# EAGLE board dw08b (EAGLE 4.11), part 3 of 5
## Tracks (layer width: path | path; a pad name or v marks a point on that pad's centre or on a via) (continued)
N_DATA07  (via drill 0.61) (continued)
  Bottom 0.305: v63.5,33.27 64.52,33.27 B20.M1 | v63.25,40.89 60.45,40.89 59.18,42.16 v58.17,42.16 | v26.42,85.85 30.48,85.85 30.73,86.11 32.26,86.11 38.61,92.46 42.16,92.46 42.42,92.2 43.18,92.2 43.43,92.46 43.69,92.46 44.45,93.22 44.45,95 44.2,95.25 44.2,98.04 44.7,98.55 v50.8,98.55 | v48.77,123.7 47.24,125.22 47.24,126.75 47.5,126.75 47.75,127 v48.77,127 | v48.77,130.05 49.02,129.79 50.55,129.79 51.05,130.3 53.34,130.3 53.85,129.79 56.9,129.79 57.4,130.3 v58.93,130.3 | v117.35,85.34 120.4,85.34 120.9,85.85 123.19,85.85 123.7,85.34 126.75,85.34 127.25,85.85 v130.3,85.85 | v130.3,82.55 133.1,82.55 133.35,82.3 136.4,82.3 136.65,82.55 139.45,82.55 139.7,82.3 142.75,82.3 143,82.55 145.8,82.55 146.05,82.3 149.1,82.3 149.35,82.55 152.15,82.55 152.4,82.3 155.45,82.3 155.7,82.55 158.5,82.55 158.75,82.3 161.8,82.3 162.05,82.55 164.85,82.55 165.35,82.04 v166.12,82.04 | v183.64,66.55 185.17,66.55 187.45,68.83 188.72,68.83 188.98,68.58 194.82,68.58 v195.07,68.83
N_DATA08  (via drill 0.61)
  Top 0.305: 193.8,61.72 193.8,16 195.33,14.48 195.33,11.68 B09.V2 | 193.8,61.72 193.8,79.76 194.56,80.52 A09.V2 | v13.97,85.85 14.22,86.11 v14.22,88.9 | v2.79,128.02 2.54,128.27 2.54,137.41 v2.79,137.67 | v26.42,139.7 v26.42,136.91 | v144.27,95.25 v144.27,98.04 | v193.55,61.72 193.8,61.72
  2 0.305: v14.22,88.9 13.97,88.65 4.32,98.3 4.32,98.55 1.02,101.85 1.02,127.25 1.78,128.02 v2.79,128.02 | v156.97,95.25 158.5,95.25 173.74,80.01 175.26,80.01 184.91,70.36 184.91,69.34 188.72,65.53 189.74,65.53 v193.55,61.72
  15 0.305: v59.18,30.99 53.34,36.83 53.34,37.08 52.58,37.85 50.8,37.85 41.66,46.99 41.66,48.51 41.15,49.02 40.64,49.02 31.5,58.17 31.5,58.67 13.72,76.45 13.72,77.22 v11.68,79.25 | v40.39,139.7 40.89,139.7 43.43,142.24 47.5,142.24 48.77,143.51 84.84,143.51 106.68,121.67 107.19,121.67 126.24,102.62 127.25,102.62 128.52,101.35 128.52,100.84 v131.57,97.79
  Bottom 0.305: v59.18,30.99 59.94,30.23 61.21,30.23 B20.N1 | v11.68,79.25 12.7,80.26 12.7,82.3 12.45,82.55 12.45,85.34 12.95,85.85 v13.97,85.85 | v2.79,137.67 3.3,138.18 20.57,138.18 21.84,136.91 v26.42,136.91 | v26.42,139.7 26.67,139.95 40.13,139.95 v40.39,139.7 | v131.57,97.79 131.83,98.04 133.1,98.04 133.6,98.55 142.49,98.55 143,98.04 v144.27,98.04 | v144.27,95.25 145.8,95.25 146.05,95 149.1,95 149.35,95.25 152.15,95.25 152.4,95 155.45,95 155.7,95.25 v156.97,95.25
N_DATA09  (via drill 0.61)
  Top 0.305: A10.D2 182.63,124.71 182.63,121.41 181.1,119.89 181.1,80.52 182.63,78.99 182.63,64.01 181.1,62.48 181.1,61.47 182.63,59.94 182.63,56.13 B10.D2 182.63,54.86 182.63,54.36 182.88,54.1 182.88,52.32 v183.13,52.07 | v66.8,12.7 66.8,21.84 66.29,22.35 66.29,26.16 65.79,26.67 B20.P1 | v71.12,9.14 v71.12,12.45 | v125.73,2.79 125.98,2.54 125.98,2.29 126.49,1.78 128.02,1.78 128.02,3.3 127.76,3.56 127.76,10.41 130.3,12.95 v130.3,13.72 | v144.02,12.7 144.53,13.21 v144.53,15.49 | v172.47,11.43 174.75,13.72 174.75,15.24 174.24,15.75 174.24,18.8 174.75,19.3 v174.75,20.57 | v175.77,32.77 175.77,35.05 174.75,36.07 174.75,43.18 175.01,43.43 v175.01,45.47
  2 0.305: v176.53,20.83 181.36,25.65 181.1,25.91 181.1,27.43 v175.77,32.77
  15 0.305: v106.68,9.14 107.19,9.14 107.44,9.4 109.22,9.4 112.52,6.1 115.82,6.1 119.13,2.79 120.14,2.79 120.4,2.54 121.92,2.54 v122.17,2.79 | v144.53,15.49 144.78,15.49 145.29,14.99 146.3,14.99 147.32,16 149.1,16 152.65,12.45 155.45,12.45 155.96,12.95 156.21,12.7 158.5,12.7 158.75,12.45 161.8,12.45 162.31,12.95 162.56,12.7 164.85,12.7 165.1,12.45 168.15,12.45 168.66,12.95 168.91,12.7 171.2,12.7 v172.47,11.43 | v175.01,45.47 175.77,45.47 182.37,52.07 v183.13,52.07
  Bottom 0.305: v66.8,12.7 69.6,12.7 69.85,12.45 v71.12,12.45 | v71.12,9.14 71.37,8.89 90.93,8.89 91.19,9.14 v106.68,9.14 | v125.73,2.79 v122.17,2.79 | v130.3,13.72 133.6,13.72 134.37,12.95 139.19,12.95 139.7,12.45 142.75,12.45 143,12.7 v144.02,12.7 | v174.75,20.57 175.01,20.83 v176.53,20.83
N_DATA10  (via drill 0.61)
  Top 0.305: v63.5,7.37 63.5,12.45 63.25,12.7 63.25,15.49 63.5,15.75 63.5,18.8 61.98,20.32 61.98,23.11 B20.R1 | v142.49,4.06 142.49,12.45 143,12.95 v143,27.43 | v184.15,28.7 184.15,31.5 183.9,31.75 183.9,34.8 184.15,35.05 184.15,37.85 183.9,38.1 183.9,41.15 v184.15,41.4 | v186.94,41.4 186.94,44.2 187.45,44.7 187.45,47.24 186.94,47.75 v186.94,49.28 | v184.15,105.66 184.15,107.7 183.9,107.95 183.9,110.74 184.15,111 184.15,114.05 183.9,114.3 183.9,117.09 184.15,117.35 184.15,117.86 185.67,119.38 185.67,121.67 A10.E2 | v165.1,104.9 164.85,104.65 164.85,101.6 165.1,101.35 165.1,98.55 163.83,97.28 v163.83,95.25 | v174.24,81.03 173.74,81.03 173.74,68.83 v174.24,68.33 | v185.67,56.9 185.67,53.09 B10.E2
  2 0.305: v186.94,49.28 186.94,51.05 186.18,51.82 B10.E2 | v174.24,68.33 180.09,62.48 180.59,62.48 181.1,61.98 181.1,61.47 v185.67,56.9
  15 0.305: v115.82,7.11 119.38,3.56 v120.9,3.56 | v160.27,95 160.27,94.49 173.74,81.03 v174.24,81.03
  Bottom 0.305: v63.5,7.37 89.41,7.37 89.92,6.86 115.57,6.86 v115.82,7.11 | v120.9,3.56 121.16,3.81 122.94,3.81 123.44,4.32 142.24,4.32 v142.49,4.06 | v143,27.43 143.76,28.19 145.8,28.19 146.3,28.7 v184.15,28.7 | v186.94,41.4 v184.15,41.4 | v184.15,105.66 183.64,105.16 183.13,105.16 182.88,104.9 v165.1,104.9 | v163.83,95.25 161.8,95.25 161.54,95 v160.27,95
N_DATA11  (via drill 0.61)
  Top 0.305: A10.H2 185.67,115.32 185.67,112.01 187.2,110.49 187.2,51.05 185.67,49.53 185.67,46.74 B10.H2 | v123.7,11.43 125.22,12.95 126.75,12.95 126.75,15.75 127,16 v127,17.02 | v135.64,11.68 136.65,12.7 v136.65,13.97 | v139.45,13.97 139.45,15.75 139.7,16 v139.7,17.78 | v177.55,13.97 177.55,14.48 178.56,15.49 178.56,17.53 v178.82,17.78 | v176.02,40.89 v176.02,39.12
  2 0.305: v110.24,16 111,16 114.55,12.45 117.35,12.45 117.86,12.95 118.11,12.7 119.38,12.7 v120.65,11.43 | v130.05,17.02 133.35,13.72 133.6,13.72 v135.64,11.68 | v178.82,17.78 177.55,19.05 177.55,20.83 182.12,25.4 182.12,25.91 181.86,26.16 181.86,27.69 177.55,32 177.55,34.8 178.05,35.31 177.8,35.56 177.8,37.34 v176.02,39.12
  15 0.305: v77.72,12.45 v69.85,20.32 | v141.99,17.78 143.26,19.05 145.8,19.05 148.08,16.76 149.35,16.76 150.62,15.49 152.15,15.49 152.91,16.26 153.16,16 155.45,16 155.96,15.49 158.5,15.49 162.05,19.05 164.85,19.05 170.43,13.46 171.45,13.46 172.47,12.45 174.5,12.45 176.28,14.22 176.53,13.97 v177.55,13.97 | v179.07,41.4 183.13,45.47 185.17,45.47 B10.H2
  Bottom 0.305: v69.85,20.32 69.6,20.57 65.79,20.57 B20.S1 | v77.72,12.45 79.25,12.45 79.5,12.7 82.3,12.7 82.55,12.45 85.6,12.45 85.85,12.7 88.65,12.7 88.9,12.45 91.95,12.45 92.2,12.7 95,12.7 95.25,12.45 98.3,12.45 98.55,12.7 101.35,12.7 101.6,12.45 104.39,12.45 106.43,14.48 107.7,14.48 109.22,16 v110.24,16 | v123.7,11.43 v120.65,11.43 | v130.05,17.02 v127,17.02 | v139.45,13.97 v136.65,13.97 | v141.99,17.78 v139.7,17.78 | v176.02,40.89 177.55,40.89 178.05,41.4 v179.07,41.4
N_DATAIN  (via drill 0.61)
  Top 0.305: v103.38,35.05 103.38,36.58 103.12,36.83 103.12,39.12 B17.K1 | v111.25,27.18 111.25,12.7 110.74,12.19 v110.74,9.4 | v212.34,7.62 212.34,12.45 212.85,12.95 212.85,28.19 211.84,29.21 211.84,33.02 B08.M2 211.07,34.04 211.07,36.32 212.85,38.1 v212.85,40.89 | v190.5,101.35 190.5,98.3 190.25,98.04 190.25,95.25 190.5,95 190.5,91.95 190.25,91.69 190.25,88.9 190.5,88.65 190.5,85.6 190.25,85.34 190.25,82.55 190.5,82.3 190.5,68.58 189.23,67.31 v189.23,64.52
  2 0.305: v111.25,27.18 v103.38,35.05 | v189.23,64.52 v212.85,40.89
  Bottom 0.305: v110.74,9.4 111,9.14 117.86,9.14 118.11,8.89 161.29,8.89 161.8,8.38 166.37,8.38 166.62,8.64 169.16,8.64 170.69,7.11 202.18,7.11 202.69,7.62 v212.34,7.62 | v190.5,101.35 193.29,101.35 193.55,101.6 196.6,101.6 196.85,101.35 199.64,101.35 199.9,101.6 202.95,101.6 203.2,101.35 205.99,101.35 207.77,103.12 210.57,103.12 A08.M2
N_EXTA0  (via drill 0.61)
  Top 0.305: A11.H2 172.97,115.32 172.97,111.51 174.5,109.98 174.5,82.8 172.97,81.28 172.97,67.06 174.5,65.53 174.5,51.05 172.97,49.53 172.97,46.74 B11.H2 172.97,45.47 v172.97,41.4 | v129.79,22.86 129.79,25.15 130.3,25.65 v130.3,26.92 | v133.1,27.18 133.1,28.45 133.6,28.96 v133.6,29.72 | v146.05,22.35 146.05,25.15 145.8,25.4 145.8,28.45 146.05,28.7 v146.05,29.72 | v148.84,29.72 148.84,31.5 149.35,32 v149.35,32.77 | v161.04,30.48 161.54,30.99 161.54,31.5 162.05,32 v162.05,40.89
  2 0.305: v133.6,29.72 134.62,28.7 135.13,28.7 140.97,22.86 v140.97,22.35 | v156.21,32 157.48,32 157.99,32.51 159,32.51 v161.04,30.48
  Bottom 0.305: v129.79,22.86 129.54,22.61 125.98,22.61 125.73,22.35 124.97,22.35 124.71,22.61 119.63,22.61 119.38,22.35 108.2,22.35 107.7,21.84 104.14,21.84 103.63,21.34 B17.S1 | v130.3,26.92 130.56,27.18 v133.1,27.18 | v146.05,22.35 v140.97,22.35 | v148.84,29.72 v146.05,29.72 | v149.35,32.77 152.65,32.77 153.42,32 v156.21,32 | v162.05,40.89 164.85,40.89 165.35,41.4 v172.97,41.4
N_EXTA1  (via drill 0.61)
  Top 0.305: v101.6,2.03 101.6,12.45 101.35,12.7 101.35,15.49 101.6,15.75 101.6,18.8 100.08,20.32 100.08,23.11 B17.R1 | v157.48,5.59 v157.48,1.27 | v167.89,5.33 167.89,12.45 168.4,12.95 168.4,17.78 168.66,18.03 168.66,23.11 168.4,23.37 168.4,24.13 168.66,24.38 168.66,29.46 168.4,29.72 168.4,30.48 168.66,30.73 168.66,35.81 168.4,36.07 168.4,36.83 168.66,37.08 168.66,42.16 168.4,42.42 168.4,43.18 168.66,43.43 168.66,48.51 168.4,48.77 168.4,49.53 168.66,49.78 v168.66,52.32 168.4,52.58 168.4,62.23 168.66,62.48 168.66,62.74 169.16,63.25 169.16,78.99 168.91,79.25 168.91,80.01 168.4,80.52 168.4,87.63 168.66,87.88 168.66,92.96 168.4,93.22 168.4,93.98 168.66,94.23 168.66,99.31 168.4,99.57 168.4,100.33 168.66,100.58 168.66,105.66 168.4,105.92 168.4,106.68 168.66,106.93 168.66,112.01 168.4,112.27 168.4,113.03 168.66,113.28 168.66,116.84 v168.4,117.09 | v172.72,117.6 172.72,119.13 172.97,119.38 172.97,121.67 A11.E2
  Bottom 0.305: v101.6,2.03 101.85,1.78 118.11,1.78 118.62,2.29 119.63,2.29 120.9,1.02 157.23,1.02 v157.48,1.27 | v157.48,5.59 157.73,5.33 v167.89,5.33 | v168.66,52.32 172.47,52.32 B11.E2 | v172.72,117.6 171.45,117.6 170.94,117.09 v168.4,117.09
N_EXTA2  (via drill 0.61)
  Top 0.305: A11.D2 169.93,124.71 169.93,121.41 171.2,120.14 171.2,80.26 169.93,78.99 169.93,63.75 171.2,62.48 171.2,61.21 169.93,59.94 169.93,56.13 B11.D2 | v103.63,30.48 103.63,30.23 103.12,29.72 103.12,27.69 B17.P1 | v117.6,31.5 117.86,31.75 117.86,35.81 117.6,36.07 117.6,36.83 117.86,37.08 117.86,42.16 117.6,42.42 117.6,43.18 117.86,43.43 117.86,48.51 117.6,48.77 117.6,49.53 117.86,49.78 117.86,54.86 117.6,55.12 v117.6,59.94 | v136.14,61.21 136.14,63.25 136.65,63.75 v136.65,72.39
  2 0.305: v148.08,72.39 149.1,72.39 163.58,57.91 v163.58,57.15
  Bottom 0.305: v103.63,30.48 103.89,30.73 104.9,30.73 105.92,31.75 107.7,31.75 107.95,31.5 111,31.5 111.25,31.75 114.05,31.75 114.3,31.5 v117.6,31.5 | v117.6,59.94 120.4,59.94 120.9,60.45 123.19,60.45 123.7,59.94 126.75,59.94 127.25,60.45 129.54,60.45 130.05,59.94 133.1,59.94 133.6,60.45 134.87,60.45 135.38,60.96 135.89,60.96 v136.14,61.21 | v136.65,72.39 136.91,72.14 147.83,72.14 v148.08,72.39 | v163.58,57.15 164.08,57.15 165.61,55.63 169.16,55.63 B11.D2
N_INIT  (via drill 0.61)
  Top 0.305: v286.51,25.15 286.26,24.89 286.26,21.84 285.5,21.08 285.5,19.05 285.75,18.8 285.75,16 284.23,14.48 284.23,11.68 B02.V2 284.23,10.41 v284.23,8.13 | v289.05,25.15 289.05,43.18 289.31,43.43 289.31,44.2 289.56,44.45 289.56,46.99 v289.81,47.24 | v293.12,47.75 v293.12,49.53 | v286.51,60.2 286.26,60.45 286.26,62.74 284.99,64.01 284.99,75.95 v285.24,76.2 | v136.14,85.85 136.14,88.65 139.7,92.2 v139.7,93.73 | v167.39,73.91 167.64,73.66 167.64,68.07 v167.39,67.82 | v249.43,12.45 249.68,12.19 249.68,8.38 v249.43,8.13
  2 0.305: v293.12,49.53 291.85,50.8 291.85,52.32 285.5,58.67 285.5,59.18 v286.51,60.2 | v131.32,84.84 129.79,84.84 128.78,85.85 127.76,85.85 127.51,86.11 126.75,85.34 123.95,85.34 120.4,88.9 118.11,88.9 117.86,89.15 117.35,88.65 114.3,88.65 112.01,90.93 110.24,90.93 A16.S2 | v167.39,67.82 173.74,61.47 173.99,61.47 174.5,60.96 174.5,59.69 175.01,59.18 176.53,59.18 v178.82,61.47 | v190.25,52.58 190.25,51.82 193.29,48.77 193.29,47.5 198.37,42.42 198.37,42.16 199.14,41.4 199.39,41.4 210.31,30.48 211.58,30.48 213.11,32 213.36,31.75 215.65,31.75 228.85,18.54 230.38,18.54 v236.47,12.45
  15 0.305: v288.54,76.2 284.48,80.26 A02.V2 | v139.7,93.73 141.22,92.2 142.75,92.2 143.26,91.69 145.8,91.69 146.56,92.46 146.81,92.2 148.59,92.2 161.8,78.99 163.83,78.99 167.39,75.44 v167.39,73.91 | v178.82,61.47 178.82,61.21 179.58,60.45 180.85,60.45 181.61,59.69 181.86,59.69 183.9,57.66 183.9,57.15 186.18,54.86 187.45,54.86 189.74,52.58 v190.25,52.58
  Bottom 0.305: v286.51,25.15 v289.05,25.15 | v289.81,47.24 291.85,47.24 292.35,47.75 v293.12,47.75 | v285.24,76.2 v288.54,76.2 | v131.32,84.84 131.83,85.34 133.1,85.34 133.6,85.85 v136.14,85.85 | v236.47,12.45 238,12.45 238.25,12.7 241.05,12.7 241.3,12.45 244.35,12.45 244.6,12.7 247.4,12.7 247.65,12.45 v249.43,12.45 | v249.43,8.13 253.24,8.13 254.25,7.11 273.81,7.11 274.57,7.87 283.97,7.87 v284.23,8.13
N_IOP1  (via drill 0.61)
  Top 0.305: A02.K2 287.27,108.97 287.27,105.66 286,104.39 286,82.55 287.27,81.28 287.27,67.06 288.8,65.53 288.8,44.7 287.27,43.18 287.27,40.39 B02.K2 | v107.95,125.48 107.95,126.75 107.7,127 107.7,130.05 v108.97,131.32 | v180.59,125.73 180.59,126.75 181.1,127.25 v181.1,128.02
  2 0.305: v107.95,125.48 109.98,123.44 109.98,122.94 A16.E2 | v108.97,131.32 110.49,129.79 114.05,129.79 114.81,130.56 115.06,130.3 117.35,130.3 117.86,129.79 119.38,129.79 121.67,132.08 122.68,132.08 124.21,133.6 124.46,133.35 126.75,133.35 127,133.1 128.78,133.1 129.79,134.11 132.33,134.11 133.35,133.1 v134.37,133.1
  15 0.305: v138.68,135.38 144.02,140.72 144.27,140.72 147.07,143.51 159,143.51 161.29,141.22 163.32,141.22 v178.82,125.73 | v182.88,128.02 199.14,111.76 200.66,111.76 207.52,104.9 208.53,104.9 v209.55,105.92
  Bottom 0.305: v134.37,133.1 135.13,133.1 137.16,135.13 138.43,135.13 v138.68,135.38 | v178.82,125.73 v180.59,125.73 | v181.1,128.02 v182.88,128.02 | v209.55,105.92 211.33,107.7 212.6,107.7 212.85,107.95 215.65,107.95 215.9,107.7 218.95,107.7 219.2,107.95 222,107.95 222.25,107.7 225.3,107.7 225.55,107.95 228.35,107.95 228.6,107.7 231.65,107.7 231.9,107.95 234.7,107.95 234.95,107.7 238,107.7 238.25,107.95 241.05,107.95 241.3,107.7 244.35,107.7 245.36,108.71 248.16,108.71 248.67,108.2 253.49,108.2 254,107.7 257.05,107.7 257.3,107.95 260.1,107.95 260.35,107.7 263.4,107.7 263.65,107.95 266.45,107.95 266.7,107.7 269.75,107.7 270,107.95 272.8,107.95 273.05,107.7 276.1,107.7 276.35,107.95 279.15,107.95 279.4,107.7 282.45,107.7 284.23,109.47 286.77,109.47 A02.K2
N_IOP2  (via drill 0.61)
  Top 0.305: v287.02,38.1 287.02,36.32 287.27,36.07 287.27,34.04 B02.M2 | v279.15,45.97 279.15,47.5 279.4,47.75 279.4,50.55 278.13,51.82 v278.13,53.59 | v280.42,55.88 v280.42,54.1 | v268.99,67.31 269.24,67.56 269.24,82.04 v268.99,82.3 | v278.13,91.19 v278.13,89.15 | v287.02,98.55 286.77,98.81 286.77,102.62 A02.M2 | v109.98,120.4 109.98,119.13 109.47,118.62 109.47,116.59 A16.H2 | v113.03,120.65 113.79,121.41 113.79,122.43 115.32,123.95 v115.32,125.73 | v141.99,123.95 142.24,124.21 142.24,125.98 142.49,126.24 142.49,126.49 143,127 v143,134.87
  2 0.305: v279.15,45.97 v287.02,38.1 | v268.99,67.31 v280.42,55.88 | v155.45,131.06 155.96,131.06 157.23,129.79 158.5,129.79 159.26,130.56 159.51,130.3 161.8,130.3 162.31,129.79 164.59,129.79 v166.12,131.32 | v237.24,130.3 241.05,126.49 241.81,126.49 264.67,103.63 265.94,103.63 266.45,103.12 266.45,102.62 274.57,94.49 v274.83,94.74
  15 0.305: v278.13,91.19 278.13,91.44 v274.83,94.74 | v116.59,125.73 117.86,127 120.4,127 120.65,126.75 123.7,126.75 124.46,127.51 124.71,127.25 126.49,127.25 127,126.75 130.05,126.75 130.56,127.25 130.81,127 132.59,127 v134.62,124.97 | v143,134.87 144.27,134.87 147.83,131.32 149.35,131.32 150.88,129.79 151.38,129.79 v151.64,130.05
  Bottom 0.305: v278.13,53.59 279.15,53.59 279.65,54.1 v280.42,54.1 | v268.99,82.3 269.49,82.3 273.56,86.36 273.56,88.65 275.34,88.65 275.84,89.15 v278.13,89.15 | v274.83,94.74 275.08,95 276.1,95 276.35,95.25 279.15,95.25 279.4,95 282.45,95 286,98.55 v287.02,98.55 | v109.98,120.4 111,120.4 111.25,120.65 v113.03,120.65 | v116.59,125.73 v115.32,125.73 | v134.62,124.97 136.65,124.97 137.67,123.95 v141.99,123.95 | v151.64,130.05 152.65,131.06 v155.45,131.06 | v166.12,131.32 168.4,131.32 169.42,130.3 v237.24,130.3
N_IOP4  (via drill 0.61)
  Top 0.305: v286.51,30.73 286.51,30.48 287.27,29.72 287.27,27.69 B02.P2 | v250.19,67.56 249.94,67.82 249.94,81.79 250.95,82.8 250.95,85.09 250.44,85.6 250.44,88.65 250.95,89.15 v250.95,91.69 | v287.02,92.2 286.77,92.46 286.77,96.27 A02.P2 | v114.05,109.47 114.05,111 114.3,111.25 114.3,114.05 114.05,114.3 114.05,117.35 114.3,117.6 v114.3,120.4 | v117.6,120.4 117.6,125.73 117.86,125.98 v117.86,128.27 | v121.67,130.3 122.17,130.81 v122.17,133.1 | v130.3,133.1 130.56,133.35 v130.56,141.73 | v218.69,133.1 218.69,130.3 219.2,129.79 219.2,127 v218.69,126.49
  2 0.305: v286.51,30.73 250.95,66.29 250.95,66.8 v250.19,67.56 | v117.86,128.27 118.87,128.27 121.16,130.56 121.41,130.3 v121.67,130.3 | v143.76,141.73 147.07,141.73 152.15,136.65 154.69,136.65 159.26,132.08 160.53,132.08 v162.81,134.37
  15 0.305: v218.69,126.49 218.69,125.22 242.57,101.35 243.08,101.35 244.09,100.33 244.09,98.81 247.4,95.5 247.4,95.25 v250.95,91.69
  Bottom 0.305: v250.95,91.69 253.75,91.69 254.25,92.2 v287.02,92.2 | v114.05,109.47 110.24,109.47 A16.K2 | v117.6,120.4 v114.3,120.4 | v122.17,133.1 123.7,133.1 123.95,133.35 126.75,133.35 127,133.1 v130.3,133.1 | v130.56,141.73 133.6,141.73 134.11,141.22 143.26,141.22 v143.76,141.73 | v162.81,134.37 164.34,134.37 165.61,133.1 168.15,133.1 168.4,133.35 171.2,133.35 171.45,133.1 174.5,133.1 174.75,133.35 177.55,133.35 177.8,133.1 180.85,133.1 181.1,133.35 183.9,133.35 184.15,133.1 187.2,133.1 187.45,133.35 190.25,133.35 190.5,133.1 193.55,133.1 193.8,133.35 196.6,133.35 196.85,133.1 199.9,133.1 200.15,133.35 202.95,133.35 203.2,133.1 206.25,133.1 206.5,133.35 209.3,133.35 209.55,133.1 212.6,133.1 212.85,133.35 215.65,133.35 215.9,133.1 v218.69,133.1
N_IRQ  (via drill 0.61)
  Top 0.305: v235.97,38.1 235.97,36.58 236.47,36.07 236.47,34.04 B06.M2 | v210.31,61.72 210.06,61.98 210.06,62.74 208.79,64.01 208.79,73.15 v209.04,73.41 | v229.36,72.9 229.36,82.3 v229.62,82.55 | v229.62,85.85 v229.62,88.65 | v236.98,92.2 v236.98,93.98 | v236.73,98.55 236.73,100.08 236.47,100.33 236.47,102.62 A06.M2 | v174.24,10.16 174.24,12.19 177.8,15.75 177.8,18.8 177.55,19.05 177.55,22.1 177.8,22.35 v177.8,24.38 | v200.15,28.19 v200.15,25.15
  2 0.305: v236.98,93.98 238.25,95.25 238.25,97.03 v236.73,98.55 | v116.33,47.75 124.46,39.62 124.46,38.86 125.22,38.1 126.75,38.1 128.78,36.07 130.3,36.07 136.14,30.23 136.14,29.72 153.42,12.45 155.45,12.45 155.96,12.95 156.21,12.7 158.5,12.7 162.05,9.14 171.45,9.14 v172.47,10.16
  15 0.305: v235.97,38.1 229.87,44.2 228.6,44.2 220.73,52.07 219.96,52.07 v210.31,61.72 | v109.47,48.01 106.68,50.8 105.92,50.8 103.89,52.83 B17.E1
  Bottom 0.305: v209.04,73.41 209.3,73.66 223.52,73.66 224.03,73.15 225.55,73.15 225.81,72.9 v229.36,72.9 | v229.62,82.55 228.35,83.82 228.35,85.34 228.85,85.85 v229.62,85.85 | v229.62,88.65 231.65,88.65 235.2,92.2 v236.98,92.2 | v109.47,48.01 112.01,48.01 112.27,47.75 v116.33,47.75 | v174.24,10.16 v172.47,10.16 | v177.8,24.38 178.31,24.89 180.34,24.89 180.85,25.4 183.9,25.4 184.15,25.15 187.2,25.15 187.45,25.4 190.25,25.4 190.5,25.15 193.55,25.15 193.8,25.4 196.6,25.4 196.85,25.15 v200.15,25.15 | v200.15,28.19 202.95,28.19 203.45,28.7 208.28,28.7 208.53,28.96 210.06,28.96 212.85,31.75 215.65,31.75 215.9,31.5 218.95,31.5 219.2,31.75 222,31.75 222.25,31.5 225.3,31.5 225.55,31.75 228.35,31.75 228.6,31.5 231.65,31.5 233.43,33.27 235.97,33.27 B06.M2
N_LINE  (via drill 0.61)
  Top 0.305: v103.38,41.4 103.38,42.93 103.12,43.18 103.12,45.47 B17.H1 | v107.7,40.89 107.7,38.1 107.95,37.85 107.95,34.8 107.7,34.54 107.7,31.75 107.95,31.5 107.95,28.45 107.7,28.19 107.7,25.4 107.95,25.15 107.95,22.1 107.7,21.84 107.7,19.05 107.95,18.8 107.95,15.75 107.7,15.49 107.7,12.7 107.95,12.45 v107.95,8.38 | v233.43,6.1 233.43,10.41 B06.V2 | v213.87,82.55 213.61,82.55 212.6,81.53 212.6,69.6 213.36,68.83 213.36,63.75 v213.61,63.5 | v205.49,63.25 205.74,62.99 205.74,61.21 205.99,60.96 205.99,60.45 206.5,59.94 206.5,55.12 206.76,54.86 206.76,49.78 206.5,49.53 206.5,48.77 206.76,48.51 206.76,43.43 206.5,43.18 206.5,42.42 206.76,42.16 206.76,37.08 206.5,36.83 206.5,36.07 206.76,35.81 206.76,30.73 206.5,30.48 206.5,29.72 206.76,29.46 206.76,25.4 v206.5,25.15 | v203.2,25.15 203.2,22.1 202.95,21.84 202.95,19.05 203.2,18.8 203.2,15.75 202.95,15.49 202.95,12.7 203.2,12.45 v203.2,6.6
  Bottom 0.305: v103.38,41.4 104.39,41.4 104.9,40.89 v107.7,40.89 | v107.95,8.38 117.6,8.38 117.86,8.13 161.04,8.13 161.54,7.62 166.62,7.62 166.88,7.87 168.91,7.87 170.43,6.35 203.2,6.35 | 203.2,6.35 208.03,6.35 208.53,6.86 210.57,6.86 211.84,5.59 224.03,5.59 224.54,6.1 v233.43,6.1 | v213.87,82.55 215.65,82.55 217.17,81.03 218.19,81.03 219.71,82.55 222,82.55 222.25,82.3 225.04,82.3 225.3,82.55 228.09,82.55 229.62,81.03 232.66,81.03 A06.V2 | v213.61,63.5 212.6,63.5 212.34,63.25 209.55,63.25 209.3,63.5 206.25,63.5 205.99,63.25 v205.49,63.25 | v206.5,25.15 v203.2,25.15 | v203.2,6.6 203.2,6.35
N_MB00  (via drill 0.61)
  Top 0.305: B03.D2 271.53,56.13 271.53,59.94 270,61.47 270,119.89 271.53,121.41 271.53,124.71 A03.D2 271.53,125.98 271.53,129.79 270,131.32 v270,139.95 | v171.45,123.95 171.45,126.75 171.2,127 171.2,130.05 171.45,130.3 171.45,133.1 171.2,133.35 v171.2,140.21
  Bottom 0.305: v171.45,123.95 165.35,123.95 164.85,123.44 161.29,123.44 160.78,122.94 A12.E2 | v171.2,140.21 171.45,140.46 252.73,140.46 253.24,139.95 v270,139.95
N_MB01  (via drill 0.61)
  Top 0.305: v164.85,115.82 164.85,117.35 165.1,117.6 165.1,120.4 164.85,120.65 164.85,123.7 165.1,123.95 165.1,126.75 164.85,127 164.85,130.05 165.1,130.3 165.1,133.1 164.85,133.35 v164.85,143.26 | v276.35,143.26 276.35,127.25 275.84,126.75 275.84,125.48 275.34,124.97 275.34,122.68 A03.E2 | v279.15,52.32 279.15,53.85 279.4,54.1 279.4,56.9 279.15,57.15 279.15,60.2 279.4,60.45 279.4,63.25 279.15,63.5 279.15,78.99 279.4,79.25 279.4,82.3 279.15,82.55 279.15,85.6 279.4,85.85 279.4,88.65 279.15,88.9 279.15,91.95 279.4,92.2 279.4,95 279.15,95.25 279.15,98.3 279.4,98.55 279.4,101.35 279.15,101.6 279.15,104.65 279.4,104.9 279.4,107.7 279.15,107.95 279.15,111 279.4,111.25 279.4,114.05 279.15,114.3 279.15,117.35 279.4,117.6 279.4,120.4 279.15,120.65 v279.15,122.17
  Bottom 0.305: v164.85,115.82 161.04,115.82 A12.H2 | v164.85,143.26 165.1,143.51 276.1,143.51 v276.35,143.26 | v279.15,52.32 275.34,52.32 B03.E2 | v279.15,122.17 275.34,122.17 A03.E2
N_MB02  (via drill 0.61)
  Top 0.305: v158.75,109.47 158.75,114.05 158.5,114.3 158.5,117.35 158.75,117.6 158.75,120.4 158.5,120.65 158.5,123.7 158.75,123.95 158.75,126.75 158.5,127 158.5,129.03 159.51,130.05 159.51,132.84 v159.77,133.1 | v163.83,133.35 164.08,133.6 164.08,141.99 v163.83,142.24 | v266.45,142.49 266.45,133.35 266.7,133.1 266.7,130.05 266.45,129.79 266.45,127 266.7,126.75 266.7,123.7 266.45,123.44 v266.45,120.65 266.7,120.4 266.7,117.6 266.45,117.35 266.45,114.3 266.7,114.05 266.7,111.25 266.45,111 266.45,107.95 266.7,107.7 266.7,104.9 266.45,104.65 266.45,101.6 266.7,101.35 266.7,98.55 266.45,98.3 266.45,95.25 266.7,95 266.7,92.2 266.45,91.95 266.45,88.9 266.7,88.65 266.7,85.85 266.45,85.6 266.45,82.55 266.7,82.3 266.7,79.25 266.45,78.99 266.45,63.5 266.7,63.25 266.7,60.45 266.45,60.2 266.45,57.15 266.7,56.9 266.7,54.1 266.45,53.85 266.45,50.8 266.7,50.55 v266.7,47.75 | v274.57,120.65 274.57,116.59 A03.H2
  Bottom 0.305: v158.75,109.47 159.77,109.47 A12.K2 | v159.77,133.1 161.8,133.1 162.05,133.35 v163.83,133.35 | v163.83,142.24 165.35,142.24 165.86,142.75 266.19,142.75 v266.45,142.49 | v266.45,120.65 266.7,120.4 269.75,120.4 270,120.65 272.8,120.65 273.05,120.4 274.32,120.4 v274.57,120.65 | v266.7,47.75 269.49,47.75 270,47.24 273.81,47.24 274.32,46.74 B03.H2
N_MB03  (via drill 0.61)
  Top 0.305: v164.85,96.77 164.85,95.25 165.1,95 165.1,91.95 164.85,91.69 164.85,88.9 165.1,88.65 165.1,85.6 164.85,85.34 164.85,82.55 165.1,82.3 v165.1,76.2 | v262.89,76.45 262.64,76.71 262.64,81.79 263.65,82.8 263.65,85.09 263.14,85.6 263.14,88.65 263.65,89.15 v263.65,98.04 | v274.32,98.55 274.07,98.81 274.07,102.62 A03.M2 | v277.11,46.23 276.86,45.97 276.86,44.45 276.61,44.2 276.61,43.43 276.35,43.18 276.35,38.35 275.84,37.85 275.84,34.29 275.34,33.78 B03.M2 | v261.11,62.23 260.86,62.48 260.86,62.74 259.59,64.01 259.59,76.2 v259.84,76.45
  2 0.305: v261.11,62.23 v277.11,46.23
  Bottom 0.305: v164.85,96.77 161.04,96.77 A12.P2 | v165.1,76.2 165.35,76.45 175.77,76.45 176.02,76.71 252.48,76.71 252.73,76.45 254.76,76.45 255.02,76.71 259.84,76.71 | 259.84,76.71 262.64,76.71 v262.89,76.45 | v263.65,98.04 266.45,98.04 266.95,98.55 v274.32,98.55 | 259.84,76.71 v259.84,76.45
N_MB03\  (via drill 0.61)
  Top 0.305: B03.K2 274.57,40.39 274.57,43.18 276.1,44.7 276.1,65.53 274.57,67.06 274.57,81.28 273.3,82.55 273.3,104.39 274.57,105.66 274.57,108.97 A03.K2 274.57,110.24 v274.57,114.05 | v160.02,106.68 160.27,106.43 160.27,103.89 A12.M2 | v155.19,111.51 155.19,114.05 155.7,114.55 v155.7,129.79 | v167.89,130.3 167.89,133.1 168.4,133.6 v168.4,138.18 | v260.1,137.92 260.1,133.35 260.35,133.1 v260.35,128.27
  2 0.305: v160.02,106.68 v155.19,111.51 | v260.35,128.27 v274.57,114.05
  Bottom 0.305: v155.7,129.79 158.5,129.79 159,130.3 161.29,130.3 161.8,129.79 164.85,129.79 165.35,130.3 v167.89,130.3 | v168.4,138.18 168.66,138.43 171.96,138.43 172.47,138.94 252.22,138.94 252.73,138.43 256.29,138.43 256.79,137.92 v260.1,137.92
N_MB04  (via drill 0.61)
  Top 0.305: v146.05,122.17 146.05,126.75 145.8,127 145.8,130.05 146.05,130.3 146.05,133.1 145.8,133.35 v145.8,140.72 | v263.65,141.73 v263.65,102.62 | v274.57,93.47 274.57,91.19 A03.S2 274.57,89.92 274.57,88.39 275.84,87.12 275.84,85.6 276.35,85.09 276.35,82.8 275.34,81.79 275.34,67.82 v275.59,67.56 | v274.32,25.15 274.32,23.62 274.57,23.37 274.57,21.34 B03.S2 | v270,25.4 270.26,25.65 270.26,29.46 270,29.72 270,30.48 270.26,30.73 270.26,35.81 270,36.07 270,36.83 270.26,37.08 270.26,42.16 270,42.42 270,43.18 270.26,43.43 270.26,48.51 270,48.77 270,49.53 270.26,49.78 270.26,54.86 270,55.12 v270,59.94 | v273.81,60.45 273.56,60.71 273.56,62.74 272.8,63.5 v272.8,67.56
  2 0.305: v265.43,102.62 v274.57,93.47
  Bottom 0.305: v146.05,122.17 147.07,122.17 A13.E2 | v145.8,140.72 146.05,140.46 157.73,140.46 158.5,141.22 164.34,141.22 164.59,141.48 165.61,141.48 166.12,141.99 263.4,141.99 v263.65,141.73 | v263.65,102.62 v265.43,102.62 | v274.32,25.15 273.05,25.15 272.8,25.4 v270,25.4 | v270,59.94 272.8,59.94 273.3,60.45 v273.81,60.45 | v275.59,67.56 v272.8,67.56
N_MB04\  (via drill 0.61)
  Top 0.305: v273.81,30.73 274.57,29.97 274.57,27.69 B03.P2 | v257.3,47.24 257.3,49.53 257.56,49.78 257.56,54.86 257.3,55.12 257.3,60.45 256.54,61.21 256.54,62.99 v256.29,63.25 | v252.22,66.8 v252.22,63.5 | v254.76,66.8 254.51,67.06 254.51,71.88 | 254.51,71.88 254.51,78.23 254.76,78.49 254.76,81.53 253.75,82.55 253.75,85.6 254,85.85 254,88.65 253.75,88.9 253.75,91.95 254,92.2 v254,95 | v254.76,71.88 254.51,71.88
  2 0.305: v257.3,47.24 v273.81,30.73
  15 0.305: v181.1,71.12 173.74,78.49 173.74,78.99 161.8,90.93 161.04,90.93 A12.S2
  Bottom 0.305: v256.29,63.25 254,63.25 253.75,63.5 v252.22,63.5 | v254.76,66.8 v252.22,66.8 | v254,95 257.05,95 257.3,95.25 260.1,95.25 260.35,95 263.4,95 263.65,95.25 266.45,95.25 266.7,95 269.75,95 271.53,96.77 274.07,96.77 A03.P2 | v181.1,71.12 181.36,71.37 190.5,71.37 191.01,70.87 199.14,70.87 199.64,71.37 203.45,71.37 203.71,71.12 204.72,71.12 204.98,71.37 209.3,71.37 209.55,71.12 221.74,71.12 222.25,71.63 223.27,71.63 223.77,71.12 229.36,71.12 229.62,70.87 240.54,70.87 241.3,71.63 247.4,71.63 247.65,71.88 v254.76,71.88
N_MB05  (via drill 0.61)
  Top 0.305: v147.83,105.92 147.83,106.43 147.57,106.68 147.57,108.97 A13.K2 | v271.02,78.99 271.53,78.99 271.53,80.26 A03.V2 | v253.75,25.15 253.75,28.45 254,28.7 254,31.5 253.75,31.75 253.75,34.8 254,35.05 254,37.85 253.75,38.1 253.75,41.15 254,41.4 254,44.2 253.75,44.45 253.75,47.5 254,47.75 254,50.55 253.75,50.8 253.75,53.85 254,54.1 254,56.9 253.75,57.15 253.75,60.2 254,60.45 254,63.25 253.75,63.5 v253.75,78.99
  2 0.305: v253.75,25.15 v265.68,13.21
  15 0.305: v147.83,105.92 v174.75,78.99
  Bottom 0.305: v271.02,78.99 v253.75,78.99 v174.75,78.99 | v265.68,13.21 265.94,13.21 267.97,11.18 270.76,11.18 B03.V2
N_MB05\  (via drill 0.61)
  Top 0.305: A03.T2 271.53,86.61 271.53,83.31 272.8,82.04 272.8,79.25 271.53,77.98 271.53,63.75 272.8,62.48 272.8,22.1 271.53,20.83 271.53,18.03 B03.T2 | v174.75,114.05 v174.75,136.4 | v238.25,136.4 v238.25,123.19
  2 0.305: v240.03,123.19 266.45,96.77 266.45,95.25 270.76,90.93 270.76,89.15 272.03,87.88 A03.T2
  Bottom 0.305: v174.75,114.05 171.45,114.05 171.2,114.3 168.4,114.3 168.15,114.05 165.1,114.05 164.85,114.3 162.05,114.3 161.8,114.05 158.75,114.05 158.5,114.3 155.7,114.3 155.45,114.05 153.42,114.05 152.4,115.06 148.84,115.06 148.59,115.32 148.08,115.32 A13.H2 | v174.75,136.4 175.01,136.65 238,136.65 v238.25,136.4 | v238.25,123.19 v240.03,123.19
N_MB06  (via drill 0.61)
  Top 0.305: v243.59,67.31 243.84,67.56 243.84,80.01 244.09,80.26 244.09,82.3 244.6,82.8 244.6,93.98 244.86,94.23 244.86,99.31 244.6,99.57 244.6,100.33 244.86,100.58 244.86,105.66 244.6,105.92 244.6,106.68 244.86,106.93 244.86,112.01 244.6,112.27 244.6,113.03 244.86,113.28 244.86,118.36 244.6,118.62 v244.6,120.65 | v214.63,69.34 v214.63,72.14
  2 0.305: v243.59,67.31 v255.02,55.88 | v197.1,69.09 v167.64,98.55
  15 0.305: v237.74,71.88 v242.32,67.31
  Bottom 0.305: v255.02,55.88 256.29,55.88 257.3,54.86 257.56,54.86 257.56,53.09 258.57,52.07 259.59,52.07 259.84,52.32 261.37,52.32 B04.E2 | v244.6,120.65 247.4,120.65 247.65,120.4 250.7,120.4 250.95,120.65 253.75,120.65 254,120.4 257.05,120.4 258.83,122.17 261.37,122.17 A04.E2 | v167.64,98.55 152.65,98.55 152.15,98.04 148.59,98.04 148.08,97.54 A13.P2 | v197.1,69.09 197.36,69.34 199.64,69.34 200.15,69.85 202.95,69.85 203.2,69.6 205.23,69.6 205.49,69.85 208.79,69.85 209.04,69.6 214.38,69.6 v214.63,69.34 | v214.63,72.14 214.88,71.88 221.49,71.88 222,72.39 225.3,72.39 225.81,71.88 229.62,71.88 229.87,71.63 237.49,71.63 v237.74,71.88 | v242.32,67.31 v243.59,67.31
N_MB06\  (via drill 0.61)
  Top 0.305: B04.D2 258.83,56.13 258.83,59.94 257.3,61.47 257.3,119.89 258.83,121.41 258.83,124.71 A04.D2 258.83,125.98 258.83,129.79 257.3,131.32 v257.3,138.94 | v149.35,142.49 149.35,108.2 148.84,107.7 148.84,104.14 148.34,103.63 A13.M2 | v161.54,142.49 v161.54,139.19
  Bottom 0.305: v149.35,142.49 149.61,142.75 161.29,142.75 v161.54,142.49 | v161.54,139.19 171.7,139.19 172.21,139.7 252.48,139.7 252.98,139.19 257.05,139.19 v257.3,138.94
N_MB07  (via drill 0.61)
  Top 0.305: B04.K2 261.87,40.39 261.87,43.18 263.4,44.7 263.4,65.53 261.87,67.06 261.87,81.28 260.6,82.55 260.6,104.39 261.87,105.66 261.87,108.97 A04.K2 261.87,110.24 v261.87,112.52 | v139.45,122.17 139.45,123.7 139.7,123.95 139.7,126.75 139.45,127 139.45,130.05 139.7,130.3 v139.7,133.1 | v155.7,133.1 155.96,133.35 155.96,138.68 157.99,140.72 159.51,140.72 v159.51,138.43 | v163.07,138.18 v163.07,136.14 | v247.4,137.16 247.4,133.35 247.65,133.1 247.65,130.05 247.4,129.79 247.4,127 v247.65,126.75
  2 0.305: v247.65,126.75 v261.87,112.52
  Bottom 0.305: v139.45,122.17 135.64,122.17 A14.E2 | v139.7,133.1 142.75,133.1 143,133.35 145.8,133.35 146.05,133.1 149.1,133.1 149.35,133.35 152.15,133.35 152.4,133.1 v155.7,133.1 | v159.51,138.43 159.77,138.18 v163.07,138.18 | v163.07,136.14 163.32,136.4 169.16,136.4 169.67,136.91 172.47,136.91 172.97,137.41 247.14,137.41 v247.4,137.16
N_MB07\  (via drill 0.61)
  Top 0.305: v261.62,50.55 261.62,49.02 261.87,48.77 261.87,46.74 B04.H2 | v251.71,52.83 v251.71,50.8 | v240.03,64.52 240.28,64.77 240.28,75.44 v240.03,75.69 | v152.4,75.18 152.4,82.3 152.15,82.55 152.15,85.6 152.4,85.85 152.4,88.65 152.15,88.9 v152.15,90.42 | v241.3,114.05 241.3,111 241.05,110.74 241.05,107.95 241.3,107.7 241.3,104.65 241.05,104.39 241.05,101.6 241.3,101.35 241.3,98.3 241.05,98.04 241.05,95.25 241.3,95 v241.3,91.69 | v238.25,91.69 238.25,82.55 237.24,81.53 237.24,75.95 v237.49,75.69
  2 0.305: v240.03,64.52 v251.71,52.83
  Bottom 0.305: v261.62,50.55 260.35,50.55 260.1,50.8 257.05,50.8 256.79,50.55 254,50.55 253.75,50.8 v251.71,50.8 | v240.03,75.69 239.78,75.95 237.49,75.95 | 237.49,75.95 176.28,75.95 176.02,75.69 166.12,75.69 165.61,75.18 v152.4,75.18 | v152.15,90.42 148.34,90.42 A13.S2 | v241.3,114.05 244.09,114.05 244.35,114.3 247.4,114.3 247.65,114.05 250.44,114.05 250.7,114.3 253.75,114.3 254,114.05 256.79,114.05 258.57,115.82 261.37,115.82 A04.H2 | v238.25,91.69 v241.3,91.69 | 237.49,75.95 v237.49,75.69
N_MB08  (via drill 0.61)
  Top 0.305: v266.45,26.92 266.45,28.45 266.7,28.7 266.7,31.5 266.45,31.75 266.45,34.8 266.7,35.05 266.7,37.85 266.45,38.1 266.45,41.15 266.7,41.4 266.7,44.2 266.45,44.45 v266.45,46.48 | v264.92,50.8 265.18,51.05 v265.18,53.59 | v267.72,57.15 v267.72,54.1 | v264.67,64.77 264.92,65.02 264.92,75.44 264.41,75.95 264.41,79.76 263.65,80.52 263.65,81.28 263.91,81.53 263.91,82.04 264.41,82.55 264.41,85.09 v264.67,85.34 | v267.72,87.63 v267.72,85.85 | v261.87,93.47 261.87,96.27 A04.P2 262.64,97.28 262.64,100.58 v263.4,101.35 | v142.49,111.25 142.49,114.05 143,114.55 143,125.73 143.26,125.98 143.26,126.24 144.02,127 v144.53,127
  2 0.305: v261.87,93.47 v267.72,87.63
  15 0.305: v267.72,57.15 267.72,57.4 262.13,62.99 v262.13,63.25 | v216.15,126.75 v242.57,100.33
  Bottom 0.305: v266.45,26.92 262.64,26.92 B04.P2 | v266.45,46.48 265.68,47.24 265.18,47.24 263.14,49.28 263.14,50.55 263.4,50.55 263.65,50.8 v264.92,50.8 | v265.18,53.59 266.45,53.59 266.95,54.1 v267.72,54.1 | v262.13,63.25 262.64,63.25 263.65,64.26 264.16,64.26 v264.67,64.77 | v264.67,85.34 266.45,85.34 266.95,85.85 v267.72,85.85 | v142.49,111.25 139.95,111.25 138.94,110.24 135.38,110.24 A14.K2 | v144.53,127 144.78,127.25 151.13,127.25 152.91,125.48 155.19,125.48 156.97,127.25 163.83,127.25 165.61,125.48 167.89,125.48 169.42,127 171.2,127 171.45,126.75 174.5,126.75 174.75,127 177.55,127 177.8,126.75 180.85,126.75 181.1,127 183.9,127 184.15,126.75 187.2,126.75 187.45,127 190.25,127 190.5,126.75 193.55,126.75 193.8,127 196.6,127 196.85,126.75 199.9,126.75 200.15,127 202.95,127 203.2,126.75 206.25,126.75 206.5,127 209.3,127 209.55,126.75 212.6,126.75 212.85,127 215.65,127 215.9,126.75 v216.15,126.75 | v242.57,100.33 242.82,100.58 244.6,100.58 245.62,101.6 247.4,101.6 247.65,101.35 250.7,101.35 250.95,101.6 253.75,101.6 254,101.35 257.05,101.35 257.3,101.6 260.1,101.6 260.35,101.35 v263.4,101.35
N_MB08\  (via drill 0.61)
  Top 0.305: v263.14,42.93 263.14,41.4 263.65,40.89 263.65,38.35 263.14,37.85 263.14,34.29 262.64,33.78 B04.M2 | v248.67,60.45 248.16,60.96 248.16,62.74 247.4,63.5 v247.4,68.83 | v250.95,68.83 250.7,69.09 250.7,81.53 251.71,82.55 251.71,85.34 v251.97,85.6 | v251.97,88.9 251.97,92.2 250.95,93.22 v250.95,98.04 250.44,98.55 250.44,101.09 250.95,101.6 v250.95,137.92 | v261.62,98.55 261.37,98.81 261.37,102.62 A04.M2 | v133.1,140.72 133.1,133.35 133.35,133.1 133.35,130.3 133.1,130.05 133.1,127 133.6,126.49 133.6,121.67 134.37,120.9 134.37,119.13 134.87,118.62 134.87,116.59 A14.H2
  15 0.305: v246.38,59.69 v263.14,42.93 | v157.48,141.73 157.99,141.73 160.53,139.19 160.53,138.68 v162.05,137.16
  Bottom 0.305: v246.38,59.69 246.63,59.94 247.4,59.94 247.9,60.45 v248.67,60.45 | v250.95,68.83 v247.4,68.83 | v251.97,85.6 250.44,87.12 250.44,88.65 250.7,88.65 250.95,88.9 v251.97,88.9 | v250.95,98.04 253.75,98.04 254.25,98.55 v261.62,98.55 | v133.1,140.72 133.35,140.46 144.02,140.46 145.29,141.73 146.3,141.73 146.81,141.22 156.97,141.22 v157.48,141.73 | v162.05,137.16 168.91,137.16 169.42,137.67 172.21,137.67 172.72,138.18 250.7,138.18 v250.95,137.92
N_MB09  (via drill 0.61)
  Top 0.305: v261.62,25.15 261.62,23.62 261.87,23.37 261.87,21.34 B04.S2 | v257.3,25.4 257.56,25.65 257.56,29.46 257.3,29.72 257.3,30.48 257.56,30.73 257.56,35.81 257.3,36.07 257.3,36.83 257.56,37.08 257.56,42.16 256.79,42.93 v256.79,43.18 | v235.71,61.72 235.46,61.98 235.46,62.74 234.19,64.01 234.19,74.42 v234.44,74.68 | v255.52,82.3 v255.52,75.69 | v262.13,88.65 261.87,88.65 261.87,89.92 A04.S2 | v136.65,143.26 136.65,112.27 137.16,111.76 137.16,108.71 136.14,107.7 136.14,104.14 135.64,103.63 A14.M2 | v162.81,143.26 v162.81,140.21 | v253.75,140.97 253.75,133.35 254,133.1 254,130.05 253.75,129.79 253.75,127 254,126.75 254,123.7 253.75,123.44 253.75,120.65 254,120.4 254,117.35 253.75,117.09 253.75,114.3 254,114.05 254,111 253.75,110.74 253.75,107.95 254,107.7 254,104.65 253.75,104.39 253.75,101.6 254.76,100.58 v254.76,99.57
  2 0.305: v254.76,99.57 260.86,93.47 260.86,92.71 262.38,91.19 A04.S2
  15 0.305: v255.02,43.18 246.13,52.07 245.36,52.07 v235.71,61.72
  Bottom 0.305: v261.62,25.15 260.35,25.15 260.1,25.4 v257.3,25.4 | v255.02,43.18 v256.79,43.18 | v234.44,74.68 240.54,74.68 241.81,75.95 252.22,75.95 252.48,75.69 v255.52,75.69 | v255.52,82.3 256.79,82.3 260.86,86.36 260.86,88.65 v262.13,88.65 | v136.65,143.26 136.91,143.51 162.56,143.51 v162.81,143.26 | v162.81,140.21 163.07,140.46 164.59,140.46 164.85,140.72 165.86,140.72 166.37,141.22 253.49,141.22 v253.75,140.97
N_MB10  (via drill 0.61)
  Top 0.305: 258.83,72.9 258.83,63.75 260.1,62.48 260.1,22.1 258.83,20.83 258.83,18.03 B04.T2 | 258.83,72.9 258.83,77.98 260.1,79.25 260.1,82.04 258.83,83.31 258.83,86.61 A04.T2 | v134.87,92.46 134.87,96.27 A14.P2 | v235.2,66.8 234.95,67.06 234.95,72.39 v235.2,72.64 | v258.57,72.9 258.83,72.9
  2 0.305: v176.02,91.69 176.02,91.19 194.31,72.9 198.88,72.9 209.3,62.48 209.3,61.21 v210.31,60.2
  Bottom 0.305: v134.87,92.46 137.41,92.46 137.67,92.2 174.24,92.2 174.75,91.69 v176.02,91.69 | v210.31,60.2 211.58,60.2 211.84,59.94 215.39,59.94 222.5,67.06 229.87,67.06 230.38,66.55 231.39,66.55 231.65,66.8 v235.2,66.8 | v235.2,72.64 235.46,72.9 238.51,72.9 238.76,72.64 240.79,72.64 241.05,72.39 247.14,72.39 247.4,72.64 254,72.64 254.25,72.9 v258.57,72.9
N_MB11  (via drill 0.61)
  Top 0.305: v254,11.18 254,12.45 v252.73,13.72 | v228.35,38.1 228.35,41.15 228.6,41.4 228.6,44.2 228.35,44.45 228.35,47.5 228.6,47.75 228.6,50.55 228.35,50.8 228.35,53.85 228.6,54.1 228.6,56.9 228.35,57.15 228.35,60.2 228.6,60.45 228.6,63.25 228.35,63.5 v228.35,68.58 | v242.82,68.58 243.08,68.83 v243.08,82.3 | v139.45,90.42 139.45,88.9 139.7,88.65 v139.7,86.11
  2 0.305: v228.35,38.1 v252.73,13.72
  15 0.305: v175.51,84.33 176.28,84.33 177.55,83.06 177.55,82.55 177.8,82.3 177.8,81.79 v189.48,70.1
  Bottom 0.305: v254,11.18 258.06,11.18 B04.V2 | v242.82,68.58 v228.35,68.58 228.09,68.83 222.5,68.83 222.25,68.58 216.92,68.58 215.14,70.36 209.3,70.36 209.04,70.61 205.23,70.61 204.98,70.36 203.45,70.36 203.2,70.61 199.9,70.61 199.39,70.1 v189.48,70.1 | v243.08,82.3 244.35,82.3 244.6,82.55 247.4,82.55 247.65,82.3 250.7,82.3 250.95,82.55 253.75,82.55 255.27,81.03 258.06,81.03 A04.V2 | v139.45,90.42 135.64,90.42 A14.S2 | v139.7,86.11 143.76,86.11 144.02,85.85 173.99,85.85 v175.51,84.33
N_MBINCR  (via drill 0.61)
  Top 0.305: A08.T2 208.03,86.61 208.03,82.8 209.3,81.53 209.3,80.26 208.03,78.99 208.03,63.75 209.3,62.48 209.3,22.1 208.03,20.83 208.03,18.03 B08.T2 | v127,2.79 v127,11.43 | v199.64,9.65 199.64,12.45 200.15,12.95 v200.15,20.07
  2 0.305: v127,11.43 125.73,12.7 125.48,12.7 124.46,13.72 124.46,14.73 122.17,17.02 121.92,17.02 120.65,18.29 120.65,18.8 114.05,25.4 114.05,25.91 111.76,28.19 111.25,28.19 104.39,35.05 104.39,35.56 102.87,37.08 100.58,37.08 B17.L1 | v151.38,5.08 151.89,5.08 155.19,8.38 169.67,8.38 170.94,7.11 180.85,7.11 v183.39,9.65
  15 0.305: v204.22,17.78 v201.93,20.07
  Bottom 0.305: v127,2.79 127.25,2.54 146.81,2.54 149.35,5.08 v151.38,5.08 | v183.39,9.65 183.64,9.4 199.39,9.4 v199.64,9.65 | v201.93,20.07 v200.15,20.07 | v204.22,17.78 204.47,17.53 207.26,17.53 B08.T2
N_RUN  (via drill 0.61)
  Top 0.305: v241.05,20.57 241.05,22.1 241.3,22.35 241.3,25.15 241.05,25.4 241.05,28.45 241.3,28.7 241.3,31.5 241.05,31.75 241.05,34.8 241.3,35.05 241.3,37.85 241.05,38.1 241.05,41.15 241.3,41.4 241.3,44.2 241.05,44.45 241.05,47.5 241.3,47.75 241.3,50.55 241.05,50.8 241.05,53.85 241.3,54.1 241.3,63.25 241.05,63.5 241.05,78.99 241.3,79.25 241.3,82.3 241.05,82.55 241.05,85.6 241.3,85.85 241.3,88.65 241.05,88.9 v241.05,90.42 | v196.6,12.7 v196.6,15.49 | v234.7,12.7 234.7,15.75 236.47,17.53 236.47,20.07 B06.S2
  15 0.305: v176.02,15.49 174.5,15.49 160.02,29.97 160.02,31.5 159,32.51 157.99,32.51 149.1,41.4 148.34,41.4 147.83,41.91 147.83,42.42 144.78,45.47 144.78,45.72 140.21,50.29 139.95,50.29 139.45,50.8 138.43,50.8 136.4,52.83 135.64,52.83 B14.E2
  Bottom 0.305: v241.05,20.57 237.24,20.57 B06.S2 | v241.05,90.42 237.24,90.42 A06.S2 | v176.02,15.49 177.55,15.49 178.05,16 193.29,16 193.8,15.49 v196.6,15.49 | v196.6,12.7 196.85,12.45 199.9,12.45 200.15,12.7 202.95,12.7 203.2,12.45 206.25,12.45 206.5,12.7 209.3,12.7 209.55,12.45 212.6,12.45 212.85,12.7 215.65,12.7 215.9,12.45 218.95,12.45 219.2,12.7 222,12.7 222.25,12.45 225.3,12.45 225.55,12.7 228.35,12.7 228.6,12.45 231.65,12.45 231.9,12.7 v234.7,12.7
N_SKIP  (via drill 0.61)
  Top 0.305: A06.K2 236.47,108.97 236.47,105.66 235.2,104.39 235.2,82.55 236.47,81.28 236.47,67.06 238,65.53 238,44.7 236.47,43.18 236.47,40.39 B06.K2 | v127.25,46.99 127.25,50.29 126.75,50.8 126.75,53.85 127,54.1 127,56.9 126.75,57.15 126.75,59.94 127.25,60.45 127.25,65.79 128.27,66.8 v128.27,72.39 | v135.38,72.39 135.64,72.64 135.64,81.79 136.65,82.8 v136.65,84.58 | v139.7,84.58 142.49,87.38 142.49,88.65 143,89.15 v143,89.92
  2 0.305: v116.84,44.2 115.82,44.2 106.68,53.34 105.41,53.34 102.62,56.13 100.58,56.13 B17.D1 | v144.78,89.92 154.69,80.01 156.21,80.01 158.24,77.98 160.53,77.98 170.18,68.33 172.72,68.33 v175.77,65.28
  15 0.305: v175.77,65.28 176.28,65.28 178.31,63.25 180.85,63.25 181.36,63.75 181.61,63.5 183.9,63.5 190.75,56.64 191.01,56.64 194.06,53.59 194.06,53.09 196.34,50.8 196.6,50.8 197.61,49.78 199.14,49.78 v214.38,34.54
  Bottom 0.305: v116.84,44.2 117.35,44.2 117.6,44.45 120.4,44.45 120.65,44.2 122.43,44.2 125.22,46.99 v127.25,46.99 | v128.27,72.39 128.52,72.64 135.13,72.64 v135.38,72.39 | v139.7,84.58 v136.65,84.58 | v144.78,89.92 v143,89.92 | v214.38,34.54 215.65,34.54 216.15,35.05 227.33,35.05 227.58,35.31 229.11,35.31 233.43,39.62 235.97,39.62 B06.K2
N_TS1  (via drill 0.61)
  Top 0.305: 284.23,68.58 284.23,63.75 285.5,62.48 285.5,22.1 284.23,20.83 284.23,18.03 B02.T2 | 284.23,68.58 284.23,77.98 285.5,79.25 285.5,82.04 284.23,83.31 284.23,86.61 A02.T2 | v123.44,99.31 123.44,101.35 123.95,101.85 123.95,106.93 124.71,107.7 124.71,109.47 v124.97,109.73 | v129.54,124.97 129.79,125.22 129.79,126.75 130.3,127.25 130.3,131.06 v130.05,131.32 | v283.97,68.58 284.23,68.58
  2 0.305: v139.7,134.37 139.95,134.37 147.57,126.75 149.1,126.75 149.61,127.25 149.86,127 151.13,127 153.42,124.71 v153.42,123.95
  15 0.305: v124.97,109.73 120.4,114.3 120.4,117.09 128.27,124.97 v129.54,124.97 | v130.05,131.32 130.3,131.32 131.83,129.79 132.84,129.79 v134.37,131.32 | v160.27,123.95 161.8,123.95 167.64,118.11 168.91,118.11 186.18,100.84 186.69,100.84 187.45,100.08 187.45,99.57 199.64,87.38 199.64,85.6 214.63,70.61 219.2,70.61 223.01,66.8 224.28,66.8 v226.31,64.77
  Bottom 0.305: v123.44,99.31 122.94,98.81 119.63,98.81 119.38,98.55 114.55,98.55 114.05,98.04 110.49,98.04 109.98,97.54 A16.P2 | v134.37,131.32 137.41,134.37 v139.7,134.37 | v153.42,123.95 v160.27,123.95 | v226.31,64.77 228.6,64.77 229.62,63.75 237.24,63.75 239.01,65.53 240.54,65.53 242.32,63.75 243.59,63.75 246.63,66.8 249.43,66.8 249.68,66.55 250.7,66.55 251.21,67.06 251.21,67.82 259.84,67.82 260.1,67.56 266.7,67.56 267.72,68.58 v283.97,68.58
N_TS3  (via drill 0.61)
  Top 0.305: v287.27,22.86 287.27,21.34 B02.S2 | v256.54,54.1 256.54,56.64 v256.29,56.9 | v265.43,63.5 265.68,63.75 265.68,76.2 v265.43,76.45 | v276.35,75.69 276.1,75.95 276.1,81.53 277.11,82.55 277.11,84.07 v277.37,84.33 | v280.42,85.85 v280.42,88.65 | v111.25,127.76 111.25,127.25 107.7,123.7 107.7,120.65 107.95,120.4 107.95,117.6 107.7,117.35 107.7,114.3 107.95,114.05 107.95,111.25 107.7,111 107.7,108.97 108.71,107.95 108.71,104.65 108.97,104.39 108.97,103.63 A16.M2 | v114.05,127.76 114.05,130.05 114.3,130.3 v114.3,131.83
  2 0.305: v287.27,22.86 282.7,27.43 282.7,27.94 v256.54,54.1 | v116.59,132.08 116.59,132.84 121.67,137.92 v121.67,142.24 | v134.37,142.49 135.89,142.49 141.73,136.65 142.75,136.65 148.08,131.32 148.84,131.32 152.15,128.02 152.15,127 177.8,101.35 180.85,101.35 181.36,101.85 181.61,101.6 182.88,101.6 185.67,98.81 186.18,98.81 192.28,92.71 v192.28,92.2
  15 0.305: v199.14,92.2 199.9,92.2 202.18,89.92 202.44,89.92 205.49,86.87 206.5,86.87 221.74,71.63 223.27,71.63 228.35,66.55 228.35,65.02 v242.82,50.55
  Bottom 0.305: v256.29,56.9 257.05,56.9 261.37,61.21 261.62,61.21 263.91,63.5 v265.43,63.5 | v265.43,76.45 265.68,76.71 269.75,76.71 270,76.45 275.59,76.45 v276.35,75.69 | v277.37,84.33 278.38,85.34 279.15,85.34 279.65,85.85 v280.42,85.85 | v280.42,88.65 282.45,88.65 284.23,90.42 286.77,90.42 A02.S2 | v114.05,127.76 v111.25,127.76 | v114.3,131.83 116.33,131.83 v116.59,132.08 | v121.67,142.24 122.17,142.75 134.11,142.75 v134.37,142.49 | v192.28,92.2 v199.14,92.2 | v242.82,50.55 244.35,50.55 244.6,50.8 247.4,50.8 247.65,50.55 249.94,50.55 251.21,51.82 252.22,51.82 254.51,54.1 v256.54,54.1
N_TT_INST  (via drill 0.61)
  Top 0.305: A06.T2 233.43,86.61 233.43,83.31 234.7,82.04 234.7,79.25 233.43,77.98 233.43,63.75 234.7,62.48 234.7,22.1 233.43,20.83 233.43,18.03 B06.T2 | v228.6,9.14 228.6,12.45 228.35,12.7 228.35,15.75 228.6,16 v228.6,17.53
  2 0.305: v179.58,10.41 161.29,28.7 159.51,28.7 159.26,28.96 158.5,28.19 157.23,28.19 152.65,32.77 151.38,32.77 147.83,36.32 147.83,36.58 146.56,37.85 146.05,37.85 145.8,38.1 144.27,38.1 143,39.37 143,39.88 138.43,44.45 136.4,44.45 135.38,45.47 B14.H2
  Bottom 0.305: v179.58,10.41 179.83,10.16 181.1,10.16 182.63,8.64 201.68,8.64 202.18,9.14 211.33,9.14 211.58,9.4 215.14,9.4 215.39,9.65 218.44,9.65 218.95,9.14 v228.6,9.14 | v228.6,17.53 232.66,17.53 B06.T2
N_WCOV  (via drill 0.61)
  Top 0.305: v177.8,95 177.8,91.95 177.55,91.69 177.55,88.9 177.8,88.65 177.8,85.6 177.55,85.34 177.55,82.55 177.8,82.3 177.8,66.8 177.55,66.55 177.55,63.5 177.8,63.25 177.8,60.2 177.55,59.94 177.55,57.15 177.8,56.9 177.8,53.85 177.55,53.59 177.55,50.8 177.8,50.55 177.8,47.5 177.55,47.24 177.55,44.45 177.8,44.2 177.8,41.15 177.55,40.89 177.55,38.1 177.8,37.85 177.8,34.8 177.55,34.54 177.55,31.75 177.8,31.5 177.8,28.45 177.55,28.19 v177.55,25.65
  Bottom 0.305: B10.P2 185.17,26.92 181.36,26.92 180.09,25.65 v177.55,25.65 140.72,25.65 139.45,26.92 135.64,26.92 B14.P2 | v177.8,95 180.59,95 182.37,96.77 185.17,96.77 A10.P2
P_3CYCLE  (via drill 0.61)
  Top 0.305: v7.87,107.95 7.87,108.97 A24.K2 | v31.75,133.1 31.75,130.3 31.5,130.05 31.5,127 31.75,126.75 31.75,123.95 31.5,123.7 31.5,120.65 31.75,120.4 31.75,117.6 31.5,117.35 31.5,114.3 31.75,114.05 31.75,111.25 31.5,111 31.5,108.2 v31.75,107.95 31.75,104.9 31.5,104.65 31.5,101.6 31.75,101.35 31.75,98.55 31.5,98.3 31.5,95.25 31.75,95 31.75,92.2 30.48,90.93 30.48,89.66 v29.72,88.9 | v56.9,134.11 v56.9,136.4 | v93.98,33.27 92.2,33.27 92.2,33.53 90.68,35.05 90.68,37.34 v89.92,38.1 | v73.15,38.1 73.15,40.89 72.64,41.4 v72.64,43.18 | v39.88,74.93 40.13,75.18 40.13,81.03 v39.88,81.28
  15 0.305: v67.82,136.4 67.82,137.41 69.34,138.94 71.88,138.94 76.71,134.11 76.71,133.6 89.15,121.16 89.66,121.16 93.73,117.09 95,117.09 95.76,117.86 96.01,117.6 97.79,117.6 v99.57,115.82 | v72.64,43.18 71.63,44.2 71.12,44.2 47.75,67.56 47.75,67.82 45.47,70.1 45.47,71.88 v42.42,74.93 | v39.88,81.28 37.59,83.57 37.59,84.58 36.83,85.34 36.58,85.34 v33.27,88.65
  Bottom 0.305: v7.87,107.95 12.45,107.95 12.7,107.7 15.75,107.7 16,107.95 18.8,107.95 19.05,107.7 22.1,107.7 22.35,107.95 25.15,107.95 25.4,107.7 28.45,107.7 28.7,107.95 v31.75,107.95 | v31.75,133.1 34.8,133.1 35.05,133.35 37.85,133.35 38.1,133.1 41.15,133.1 41.4,133.35 44.2,133.35 44.45,133.1 47.5,133.1 47.75,133.35 50.55,133.35 50.8,133.1 53.85,133.1 54.61,133.86 56.64,133.86 v56.9,134.11 | v56.9,136.4 57.15,136.65 67.56,136.65 v67.82,136.4 | v99.57,115.82 102.62,115.82 A17.H1 | v93.98,33.27 96.27,33.27 B17.M2 | v89.92,38.1 85.6,38.1 85.34,37.85 82.55,37.85 82.3,38.1 79.25,38.1 78.99,37.85 76.2,37.85 75.95,38.1 v73.15,38.1 | v42.42,74.93 v39.88,74.93 | v33.27,88.65 31.75,88.65 31.5,88.9 v29.72,88.9
P_AC00  (via drill 0.61)
  Top 0.305: v87.63,57.15 87.63,58.67 87.38,58.93 87.38,61.21 B18.B1 | v37.85,122.17 37.85,123.44 38.1,123.7 38.1,126.75 36.58,128.27 36.58,131.06 A22.B1 | v66.29,93.73 66.29,92.2 66.8,91.69 v66.8,83.82
  2 0.305: v37.85,122.17 37.85,121.67 65.79,93.73 v66.29,93.73
  15 0.305: v66.8,83.82 67.31,83.82 71.37,79.76 71.37,79.5 77.22,73.66 77.22,69.85 85.6,61.47 86.61,61.47 B18.B1
  Bottom 0.305: v87.63,57.15 87.88,57.4 100.33,57.4 102.11,55.63 105.66,55.63 B16.D2
P_AC01  (via drill 0.61)
  Top 0.305: v91.69,55.88 91.69,56.9 92.2,57.4 v92.2,60.2 | v36.58,121.92 36.58,124.71 A22.D1
  2 0.305: v36.58,121.92 78.99,79.5 78.99,78.49 90.68,66.8 91.44,66.8 98.04,60.2 v98.3,60.2
  15 0.305: v98.3,60.2 v106.17,52.32
  Bottom 0.305: v91.69,55.88 90.17,55.88 89.92,55.63 87.88,55.63 B18.D1 | v92.2,60.2 92.46,59.94 95,59.94 95.5,60.45 98.04,60.45 v98.3,60.2 | v106.17,52.32 108.97,52.32 B16.E2
P_AC02  (via drill 0.61)
  Top 0.305: v95,52.07 95,50.8 95.25,50.55 v95.25,48.01 | v41.4,104.65 41.4,106.68 41.66,106.93 41.66,112.01 41.4,112.27 41.4,113.03 41.66,113.28 41.66,116.84 40.89,117.6 40.89,121.41 40.39,121.92 A22.E1
  15 0.305: v41.4,104.65 49.78,96.27 49.78,96.01 60.96,84.84 60.96,83.57 61.98,82.55 62.23,82.55 63.75,81.03 63.75,79.25 64.26,78.74 64.77,78.74 75.95,67.56 75.95,65.02 87.38,53.59 89.15,53.59 89.92,52.83 B18.E1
